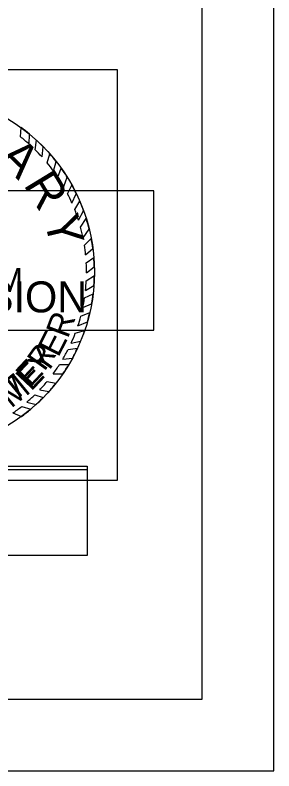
# Model space of a CAD drawing. Extents: x -0.25 to 1.92, y 0 to 0.95.
# Drawn here: x 1.3416 to 1.4167, y 0 to 0.2194 of the extents above; entities that cross this region are included whole.
import ezdxf

# ---------------------------------------------------------------- set-up
doc = ezdxf.new("R2010")
doc.units = 0
for name, color, linetype in [('DSN_DRFT_Guideline-No-Plot', 7, 'Continuous'), ('SHET_Border-Lines', 7, 'Continuous'), ('SHET_Stamp-Prelim', 7, 'Continuous'), ('STAMP_PE DIG SIG', 7, 'Continuous'), ('STAMP_PE_BACKGROUND', 7, 'Continuous'), ('STAMP_PE_FOSTER', 7, 'Continuous'), ('STAMP_PE_SEAL-INFO', 7, 'Continuous'), ('STAMP_PE_TAEGTMEYER', 7, 'Continuous'), ('STAMP_PRELIMINARY', 7, 'Continuous')]:
    doc.layers.add(name, color=color, linetype=linetype)

msp = doc.modelspace()

# ---------------------------------------------------------------- linework, layer by layer
at = {"layer": 'DSN_DRFT_Guideline-No-Plot'}
msp.add_lwpolyline([(0, 0), (1.416666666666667, 0), (1.416666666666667, 0.9166666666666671), (0, 0.9166666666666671)], close=True, dxfattribs=at)
at = {"layer": 'SHET_Border-Lines'}
msp.add_lwpolyline([(0.02083333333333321, 0.02083333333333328), (1.3958333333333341, 0.02083333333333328), (1.3958333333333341, 0.8958333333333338), (0.02083333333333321, 0.8958333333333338)], close=True, dxfattribs=at)
at = {"layer": 'SHET_Stamp-Prelim'}
msp.add_lwpolyline([(1.2006351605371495, 0.127997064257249), (1.3818064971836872, 0.127997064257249), (1.3818064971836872, 0.16844934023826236), (1.2006351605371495, 0.16844934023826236)], close=True, dxfattribs=at)
at = {"layer": 'STAMP_PE DIG SIG'}
msp.add_lwpolyline([(1.2625000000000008, 0.08749999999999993), (1.3625000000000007, 0.08749999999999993), (1.3625000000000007, 0.062499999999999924), (1.2625000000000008, 0.062499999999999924)], close=True, dxfattribs=at)
at = {"layer": 'STAMP_PE_BACKGROUND'}
for points in [[(1.3712499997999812, 0.20354166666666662), (1.2520833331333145, 0.20354166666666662), (1.2520833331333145, 0.08437499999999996), (1.3712499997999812, 0.08437499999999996)], [(1.2625000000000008, 0.08843749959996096), (1.3625000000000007, 0.08843749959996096), (1.3625000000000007, 0.062499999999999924), (1.2625000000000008, 0.062499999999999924)]]:
    msp.add_lwpolyline(points, close=True, dxfattribs=at)
at = {"layer": 'STAMP_PE_SEAL-INFO'}
for p, q in [((1.3431312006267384, 0.18405361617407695), (1.3433223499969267, 0.1867756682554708)), ((1.345625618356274, 0.18197317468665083), (1.3457347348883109, 0.18489311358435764)), ((1.3473716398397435, 0.18034078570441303), (1.3477586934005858, 0.18312570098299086)), ((1.3493777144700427, 0.17825515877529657), (1.349749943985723, 0.18119380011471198)), ((1.3509076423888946, 0.1764874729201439), (1.351669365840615, 0.1791199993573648)), ((1.3527177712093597, 0.174156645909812), (1.3534723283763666, 0.17694663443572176)), ((1.35394615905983, 0.17239577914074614), (1.3549390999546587, 0.1749843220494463)), ((1.3556677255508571, 0.16961743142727), (1.3566877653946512, 0.17236185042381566)), ((1.3567821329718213, 0.1675702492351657), (1.3580476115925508, 0.17005208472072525)), ((1.358071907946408, 0.1648658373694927), (1.3593364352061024, 0.1675737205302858)), ((1.358856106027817, 0.16298184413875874), (1.36033068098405, 0.16540475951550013)), ((1.3599451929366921, 0.15991531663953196), (1.3614566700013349, 0.16256575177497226)), ((1.3605469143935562, 0.1578784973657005), (1.3621878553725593, 0.16040546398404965)), ((1.361289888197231, 0.15475750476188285), (1.3630707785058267, 0.15725240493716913)), ((1.361675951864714, 0.15263366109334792), (1.3636501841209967, 0.15460656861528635)), ((1.362045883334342, 0.1497893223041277), (1.3641275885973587, 0.15166667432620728)), ((1.362226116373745, 0.14745333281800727), (1.3644061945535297, 0.14908358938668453)), ((1.362296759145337, 0.14455951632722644), (1.3645598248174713, 0.14635636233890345)), ((1.3622347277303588, 0.14229607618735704), (1.3645747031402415, 0.14384355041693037)), ((1.3620119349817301, 0.13946818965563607), (1.364437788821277, 0.14090068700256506)), ((1.3617300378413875, 0.13729670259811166), (1.3642048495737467, 0.13852411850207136)), ((1.3612231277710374, 0.13450439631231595), (1.3637650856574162, 0.13559576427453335)), ((1.360621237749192, 0.1319808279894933), (1.3632555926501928, 0.13310648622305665)), ((1.35979979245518, 0.129219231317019), (1.3625386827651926, 0.1303416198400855)), ((1.359047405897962, 0.12709674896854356), (1.3617437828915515, 0.12782925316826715)), ((1.3578509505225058, 0.12422318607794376), (1.3605781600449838, 0.12476258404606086)), ((1.3569513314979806, 0.12234505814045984), (1.3596778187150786, 0.12272524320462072)), ((1.355430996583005, 0.11955873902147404), (1.3582298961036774, 0.11986276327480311)), ((1.3544708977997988, 0.11799213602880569), (1.3571381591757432, 0.11795683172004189)), ((1.3525738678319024, 0.1152306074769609), (1.3553925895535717, 0.11524679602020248)), ((1.350853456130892, 0.11303031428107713), (1.353432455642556, 0.11258595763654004)), ((1.3487131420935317, 0.11061010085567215), (1.3513780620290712, 0.1101337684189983)), ((1.347289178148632, 0.10916184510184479), (1.3497523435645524, 0.10839198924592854)), ((1.3435092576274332, 0.10582761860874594), (1.3461231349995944, 0.10501531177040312)), ((1.345021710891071, 0.10708080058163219), (1.3476546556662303, 0.10636220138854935)), ((1.3409364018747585, 0.10391206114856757), (1.3433867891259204, 0.10285504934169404))]:
    msp.add_line(p, q, dxfattribs=at)
for radius, start, end in [(0.05208333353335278, 50.34919923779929, 53.715927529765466), (0.04979730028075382, 48.301629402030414, 52.0395271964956), (0.05208333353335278, 44.34049610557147, 47.392920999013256), (0.04979730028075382, 42.221157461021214, 45.55119386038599), (0.05208333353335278, 38.12472275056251, 41.2315730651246), (0.04979730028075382, 36.135025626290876, 39.53106373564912), (0.05208333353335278, 31.96138013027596, 35.42937309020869), (0.04979730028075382, 29.903213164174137, 33.66454441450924), (0.05208333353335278, 25.939091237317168, 29.012473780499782), (0.04979730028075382, 23.77322286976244, 27.221139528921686), (0.05208333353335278, 19.953806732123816, 23.314091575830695), (0.04979730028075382, 17.68022309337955, 21.42508660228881), (0.05208333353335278, 13.842052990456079, 17.444684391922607), (0.04979730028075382, 11.544448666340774, 15.236388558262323), (0.05208333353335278, 7.585188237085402, 10.862114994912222), (0.04979730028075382, 5.7598993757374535, 9.06055796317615), (0.04979730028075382, 359.7328912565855, 3.0639197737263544), (0.05208333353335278, 1.7215475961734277, 4.7268136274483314), (0.05208333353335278, 355.71562332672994, 358.956939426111), (0.04979730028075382, 353.86318650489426, 357.12741991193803), (0.05208333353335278, 349.83046937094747, 353.08845194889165), (0.04979730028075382, 348.07782395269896, 351.34354893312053), (0.04979730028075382, 341.7769864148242, 345.0924752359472), (0.05208333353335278, 343.8924710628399, 347.03501976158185), (0.05208333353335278, 337.3836727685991, 340.99332282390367), (0.04979730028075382, 335.60379596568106, 339.1857838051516), (0.04979730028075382, 329.55488416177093, 333.20757358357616), (0.05208333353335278, 331.4037138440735, 334.933154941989), (0.04979730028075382, 323.58513069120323, 327.44068976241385), (0.05208333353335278, 325.4405170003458, 328.9872482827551), (0.04979730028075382, 316.6530849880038, 320.3710862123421), (0.05208333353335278, 318.2845512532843, 321.8042854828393), (0.04979730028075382, 310.7743619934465, 314.31605044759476), (0.05208333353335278, 312.45177291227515, 315.66328088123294), (0.04979730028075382, 304.8229923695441, 308.51427595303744), (0.05208333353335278, 306.37206251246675, 310.20798964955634)]:
    msp.add_arc((1.3125000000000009, 0.14479166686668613), radius, start, end, dxfattribs=at)
at = {"layer": 'STAMP_PRELIMINARY'}
msp.add_circle((1.3125000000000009, 0.14479166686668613), 0.05208333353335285, dxfattribs=at)

# ---------------------------------------------------------------- texts
at = {"layer": 'SHET_Stamp-Prelim'}
msp.add_text('SUBJECT TO REVISION', height=0.009, dxfattribs=at).set_placement((1.2267484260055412, 0.13311013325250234))
at = {"layer": 'STAMP_PE_FOSTER'}
for s, height, rotation, p in [('R', 0.006704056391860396, 54.50309997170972, (1.350066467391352, 0.11580297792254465)), ('E', 0.006704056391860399, 46.96130660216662, (1.3460238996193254, 0.11121650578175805)), ('T', 0.006704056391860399, 39.41937898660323, (1.3412284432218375, 0.1070258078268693))]:
    msp.add_text(s, height=height, rotation=rotation, dxfattribs=at).set_placement(p)
at = {"layer": 'STAMP_PE_TAEGTMEYER'}
for s, height, rotation, p in [('R', 0.006983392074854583, 69.57000985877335, (1.3568870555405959, 0.12531919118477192)), ('E', 0.00698339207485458, 63.09839547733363, (1.3541015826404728, 0.11983535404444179)), ('Y', 0.006983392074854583, 53.99864225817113, (1.3503639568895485, 0.11458068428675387)), ('E', 0.006983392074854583, 46.80937910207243, (1.3462349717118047, 0.11002725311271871)), ('M', 0.00698339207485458, 39.30004668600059, (1.3404223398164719, 0.1051158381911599))]:
    msp.add_text(s, height=height, rotation=rotation, dxfattribs=at).set_placement(p)
at = {"layer": 'STAMP_PRELIMINARY'}
for s, height, rotation, p in [('A', 0.010056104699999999, 315.65789090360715, (1.3362148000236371, 0.17755060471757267)), ('R', 0.010056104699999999, 301.38306156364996, (1.343856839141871, 0.17020900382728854)), ('Y', 0.010056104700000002, 283.25926303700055, (1.3499420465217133, 0.16022803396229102))]:
    msp.add_text(s, height=height, rotation=rotation, dxfattribs=at).set_placement(p)
msp.add_text('PICKERING FIRM', height=0.006983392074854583, dxfattribs=at).set_placement((1.2670979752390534, 0.1389994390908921))

doc.saveas('drawing.dxf')
